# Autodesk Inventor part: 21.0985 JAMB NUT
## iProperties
Created: 2007-07
Part Number: 21.0985 JAMB NUT
Document SubType Name: Modeling
Designer: Andy Moles
Material: Steel
Mass: 8.25011 g
Surface Area: 9.72761 cm^2
Volume: 1.05097 cm^3
Density: 7.85 g/cm^3
Author: Andy Moles
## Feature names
1. Extrusion1
2. Fillet2
